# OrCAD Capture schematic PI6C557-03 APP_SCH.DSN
size A; title: PI6C557-03 Application Schematic; rev: A; note: Diodes Inc. Clock IC Application Engineering
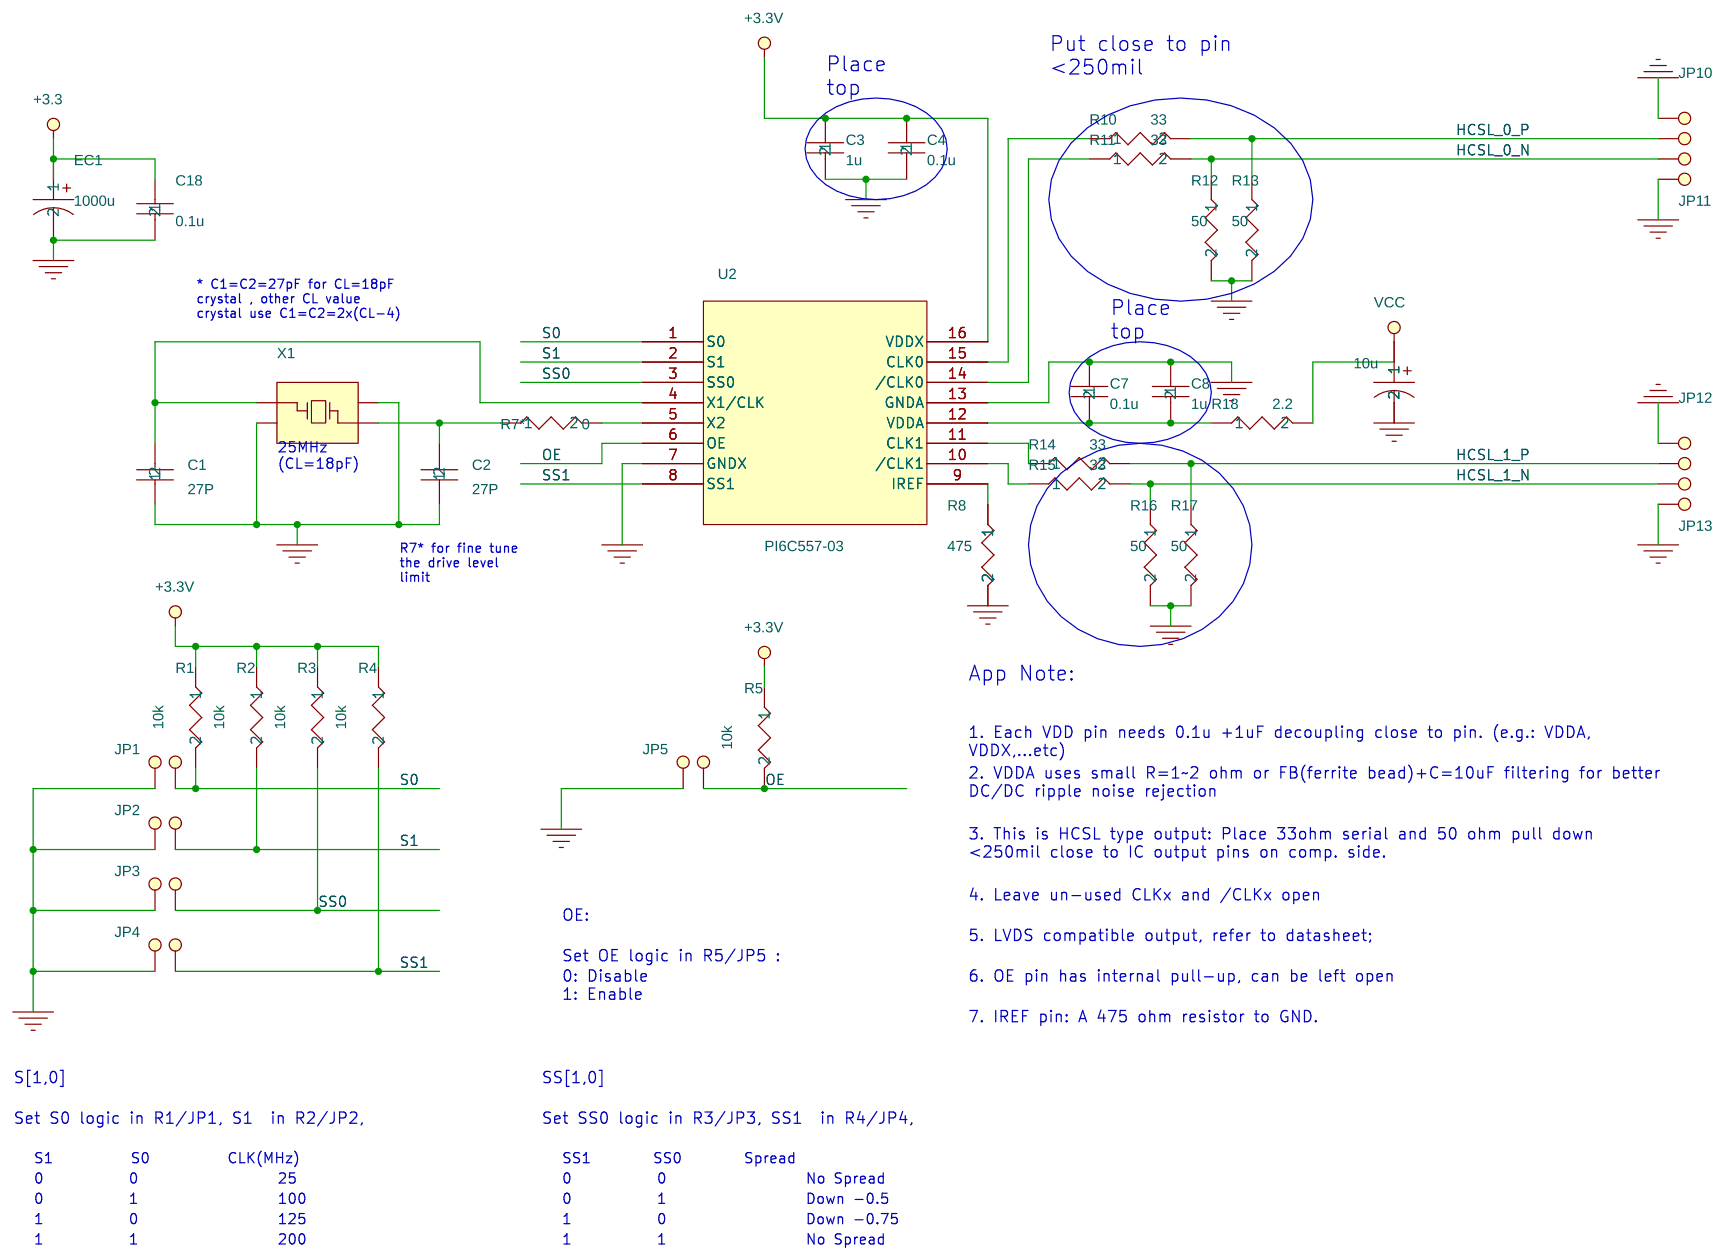
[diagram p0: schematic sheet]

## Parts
C1  27P  [CC_0402]
C2  27P  [CC_0402]
C3  1u  [CC_0402]
C4  0.1u  [CC_0402]
C7  0.1u  [CC_0402]
C8  1u  [CC_0402]
C18  0.1u  [CC_0402]
EC1  1000u  [CAP1000UF]
EC1#2  10u  [CAP1000UF]
JP1  2x1 Pin Header  [2x1 Pin Header]
JP2  2x1 Pin Header  [2x1 Pin Header]
JP3  2x1 Pin Header  [2x1 Pin Header]
JP4  2x1 Pin Header  [2x1 Pin Header]
JP5  2x1 Pin Header  [2x1 Pin Header]
JP10  2x1 Pin Header  [2x1 Pin Header]
JP11  2x1 Pin Header  [2x1 Pin Header]
JP12  2x1 Pin Header  [2x1 Pin Header]
JP13  2x1 Pin Header  [2x1 Pin Header]
R1  10k  [R_0402]
R2  10k  [R_0402]
R3  10k  [R_0402]
R4  10k  [R_0402]
R5  10k  [R_0402]
R7*  0  [R_0402]
R8  475  [R_0402]
R10  33  [R_0402]
R11  33  [R_0402]
R12  50  [R_0402]
R13  50  [R_0402]
R14  33  [R_0402]
R15  33  [R_0402]
R16  50  [R_0402]
R17  50  [R_0402]
R18  2.2  [R_0402]
U2  PI6C557-03  [16]
X1  Crystal_4P_SMD  [CYRSTAL@SM4]

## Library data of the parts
C1 = C_0.1u_0402_1
C2 = C_0.1u_0402_4
C3 = C_0.1u_0402_6
C4 = C_0.1u_0402
C7 = C_0.1u_0402_5
C8 = C_0.1u_0402_3
C18 = C_0.1u_0402_2
EC1 EC1#2 = C_alum_1000u
JP1-JP5 JP10-JP13 = 2x1_Pin_Header
R1 = R_0402_6
R2 = R_0402_12
R3 = R_0402_9
R4 = R_0402_8
R5 = R_0402_5
R7* = R_0402_15
R8 = R_0402_2
R10 = R_0402_10
R11 = R_0402_4
R12 = R_0402
R13 = R_0402_7
R14 = R_0402_3
R15 = R_0402_14
R16 = R_0402_1
R17 = R_0402_11
R18 = R_0402_13
U2 = PI6C557-03A_0
X1 = Crystal_4P_SMD

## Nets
+3.3V: C3.1 C4.1 EC1#2.1 R1.1 R2.1 R3.1 R4.1 R5.1 U2.16(VDDX)
GND: C1.1 C2.1 C3.2 C4.2 C7.1 C8.1 C18.2 EC1.2 EC1#2.2 JP1.1 JP2.1 JP3.1 JP4.1 JP5.1 JP10.1 JP11.2 JP12.1 JP13.2 R8.2 R12.2 R13.2 R16.2 R17.2 U2.7(GNDX) U2.13(GNDA) X1.2 X1.4
+3.3: C18.1 EC1.1
HCSL_0_N: JP11.1 R11.2 R12.1
HCSL_0_P: JP10.2 R10.2 R13.1
HCSL_1_N: JP13.1 R15.2 R16.1
HCSL_1_P: JP12.2 R14.2 R17.1
OE: JP5.2 R5.2 U2.6(OE)
S0: JP1.2 R1.2 U2.1(S0)
S1: JP2.2 R2.2 U2.2(S1)
SS0: JP3.2 R3.2 U2.3(SS0)
SS1: JP4.2 R4.2 U2.8(SS1)
N4601713: C7.2 C8.2 R18.1 U2.12(VDDA)
N4601789: R8.1 U2.9(IREF)
N4601809: R14.1 U2.11(CLK1)
N4601817: R15.1 U2.10(/CLK1)
N4602005: R10.1 U2.15(CLK0)
N4602009: R11.1 U2.14(/CLK0)
N4602245: R7*.2 U2.5(X2)
N4602249: C2.2 R7*.1 X1.1
N4602267: C1.2 U2.4(X1/CLK) X1.3

Not connected (* = marked no-connect by the designer): R18 2

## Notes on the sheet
- Put close to pin
  <250mil
- Place
  top
- * C1=C2=27pF for CL=18pF
  crystal , other CL value
  crystal use C1=C2=2x(CL-4)
- Place
  top
- 25MHz
  (CL=18pF)
- R7* for fine tune
  the drive level
  limit
- App Note:
- 1. Each VDD pin needs 0.1u +1uF decoupling close to pin. (e.g.: VDDA,
  VDDX,...etc)
- 2. VDDA uses small R=1~2 ohm or FB(ferrite bead)+C=10uF filtering for better
  DC/DC ripple noise rejection
- 3. This is HCSL type output: Place 33ohm serial and 50 ohm pull down
  <250mil close to IC output pins on comp. side.
- 4. Leave un-used CLKx and /CLKx open
- OE:
- 5. LVDS compatible output, refer to datasheet;
- Set OE logic in R5/JP5 :
- 0: Disable
  1: Enable
- 6. OE pin has internal pull-up, can be left open
- 7. IREF pin: A 475 ohm resistor to GND.
- S[1,0]
- SS[1,0]
- Set S0 logic in R1/JP1, S1  in R2/JP2,
- Set SS0 logic in R3/JP3, SS1  in R4/JP4,
- S1          S0          CLK(MHz)
- SS1        SS0        Spread
- 0           0
- 25
- 0           0
- No Spread
- 0           1
- 100
- 0           1
- Down -0.5
- 1           0
- 125
- 1           0
- Down -0.75
- 1           1
- 200
- 1           1
- No Spread
